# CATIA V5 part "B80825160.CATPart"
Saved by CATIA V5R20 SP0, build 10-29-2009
Part number: B80825160
Revision: 4
Definition: design
Nomenclature: B80825160
Source: made
Description: NOT SPECIFIED
Bounding box of the stored display mesh (mm): x -15 to 15, y -15 to 15, z 0 to 160
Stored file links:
  C:\Users\Raffaele\Desktop\3D X SITO CF\BOLEX\4-PILLAR REF 808\B80825160.CATPart
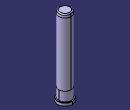
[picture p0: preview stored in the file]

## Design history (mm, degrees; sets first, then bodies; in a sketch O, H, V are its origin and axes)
Body1 "MANIFOLD_SOLID_BREP #450" (main body)
  Solid1: solid without history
